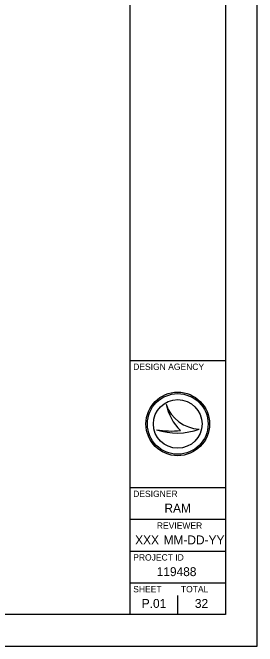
# Model space of a CAD drawing. Extents: x -7.1 to 34, y 0 to 22.
# Drawn here: x 30.16 to 34, y 0 to 9.97 of the extents above; entities that cross this region are included whole.
import ezdxf

# ---------------------------------------------------------------- set-up
doc = ezdxf.new("R2010")
doc.units = 0
for name, color, linetype in [('SH_Border', 7, 'Continuous'), ('SH_Cut_Line', 7, 'Continuous'), ('SH_Data', 7, 'Continuous')]:
    doc.layers.add(name, color=color, linetype=linetype)

msp = doc.modelspace()

# ---------------------------------------------------------------- linework, layer by layer
at = {"layer": 'SH_Border'}
for p, q in [((32, 0.5), (32, 21.5)), ((32, 4.5), (33.5, 4.5)), ((32, 2.5), (33.5, 2.5)), ((32, 2), (33.5, 2)), ((32, 1.5), (33.5, 1.5)), ((32, 1), (33.5, 1))]:
    msp.add_line(p, q, dxfattribs=at)
msp.add_lwpolyline([(1.5, 21.5), (33.5, 21.5), (33.5, 0.5), (1.5, 0.5)], close=True, dxfattribs=at)
at = {"layer": 'SH_Cut_Line'}
msp.add_lwpolyline([(0, 0), (34, 0), (34, 22), (0, 22)], close=True, dxfattribs=at)
at = {"layer": 'SH_Data'}
for p, q in [((32.5674, 3.8096), (32.5675, 3.8096)), ((32.75, 3.5), (32.75, 3.5)), ((32.4172, 3.4095), (32.4172, 3.4095)), ((33.0873, 3.4185), (33.0873, 3.4185)), ((32.75, 0.5), (32.75, 0.8)), ((32.375, 0.675), (32.375, 0.675))]:
    msp.add_line(p, q, dxfattribs=at)
for radius in [0.5, 0.4768, 0.4768, 0.3822]:
    msp.add_circle((32.75, 3.5), radius, dxfattribs=at)
for centre, radius, start, end in [((33.1159, 3.9976), 0.5798, 198.92567, 198.93195), ((33.3467, 3.9701), 0.7956, 191.63793, 191.64215), ((33.1159, 3.9976), 0.5798, 198.93195, 267.16574), ((33.3467, 3.9701), 0.7956, 191.64215, 226.09467), ((32.7394, 4.37), 1.0131, 251.45764, 290.08324), ((32.648, 4.6543), 1.2661, 259.49639, 259.49952), ((32.7394, 4.37), 1.0131, 251.45274, 251.45764), ((32.648, 4.6543), 1.2661, 259.49952, 276.66723)]:
    msp.add_arc(centre, radius, start, end, dxfattribs=at)

# ---------------------------------------------------------------- texts
for s, height, p in [('DESIGN AGENCY', 0.1, (32.05, 4.35)), ('DESIGNER', 0.1, (32.05, 2.35)), ('RAM', 0.14, (32.5412, 2.105)), ('REVIEWER', 0.1, (32.4218, 1.85)), ('XXX', 0.14, (32.0809, 1.605)), ('MM-DD-YY', 0.14, (32.5273, 1.605)), ('PROJECT ID', 0.1, (32.05, 1.35)), ('119488', 0.14, (32.4193, 1.105)), ('SHEET', 0.1, (32.05, 0.85)), ('TOTAL', 0.1, (32.8, 0.85)), ('P.01', 0.14, (32.1844, 0.605)), ('32', 0.14, (33.0194, 0.605))]:
    msp.add_text(s, height=height, dxfattribs=at).set_placement(p)

doc.saveas('drawing.dxf')
